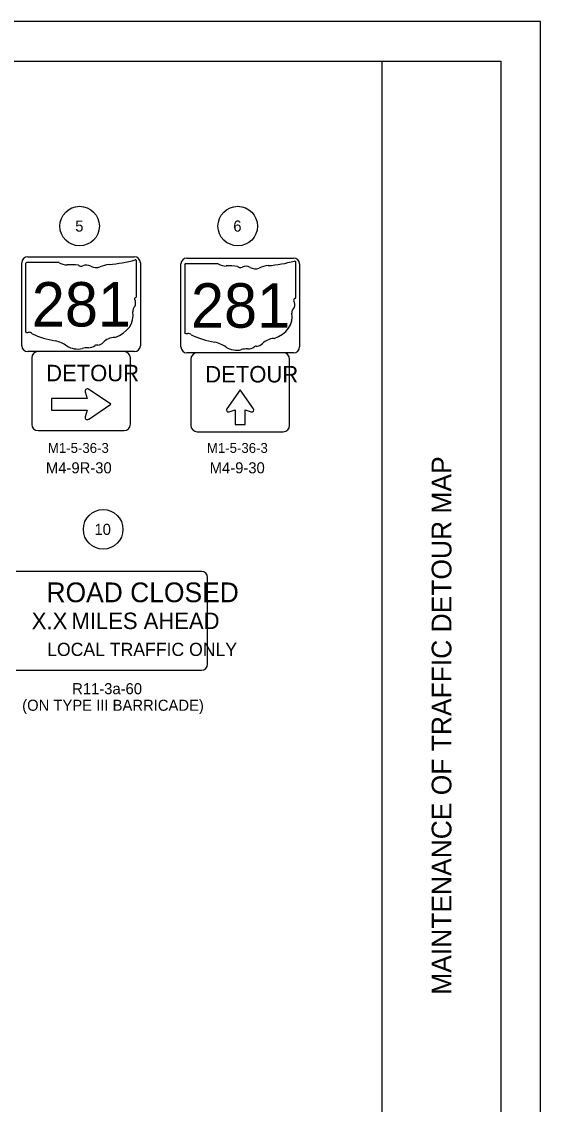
# Model space of a CAD drawing. Extents: x 0 to 680, y 0 to 834.
# Drawn here: x 548.7 to 680, y 165.9 to 440 of the extents above; entities that cross this region are included whole.
import ezdxf

# ---------------------------------------------------------------- set-up
doc = ezdxf.new("R2010")
doc.units = 0
for name, color, linetype in [('SH_Border', 7, 'Continuous'), ('SH_Cut_Line', 7, 'Continuous'), ('SH_Data', 7, 'Continuous'), ('SH_Text', 7, 'Continuous'), ('SN_P_Signs', 7, 'Continuous'), ('SN_P_Text', 7, 'Continuous'), ('SN_X_Public', 7, 'Continuous')]:
    doc.layers.add(name, color=color, linetype=linetype)

msp = doc.modelspace()

# ---------------------------------------------------------------- linework, layer by layer
at = {"layer": 'SH_Border'}
msp.add_line((640, 10), (640, 430), dxfattribs=at)
msp.add_lwpolyline([(30, 430), (670, 430), (670, 10), (30, 10)], close=True, dxfattribs=at)
at = {"layer": 'SH_Cut_Line'}
msp.add_lwpolyline([(0, 0), (680, 0), (680, 440), (0, 440)], close=True, dxfattribs=at)
at = {"layer": 'SH_Text'}
for centre in [(563.41, 388.25), (603.41, 388.25), (569.36, 311.46)]:
    msp.add_circle(centre, 5, dxfattribs=at)
at = {"layer": 'SN_P_Signs'}
for p, q in [((549.71, 378.68), (549.71, 361.61)), ((558.23, 378.98), (549.99, 378.98)), ((577.84, 370.47), (577.84, 379.4)), ((589.99, 378.39), (589.99, 361.31)), ((598.5, 378.68), (590.27, 378.68)), ((618.11, 370.17), (618.11, 379.1)), ((577.84, 370.47), (577.84, 370.47)), ((618.11, 370.17), (618.11, 370.17)), ((564.79, 346.28), (565.34, 344.58)), ((571.27, 343.12), (565.66, 346.93)), ((565.34, 344.58), (556.28, 344.58)), ((556.28, 344.58), (556.28, 341.66)), ((565.66, 339.31), (571.27, 343.12)), ((556.28, 341.66), (565.34, 341.66)), ((565.34, 341.66), (564.79, 339.96))]:
    msp.add_line(p, q, dxfattribs=at)
for points in [[(548.78, 357.95), (548.78, 378.95)], [(550.28, 380.45), (577.28, 380.45)], [(578.78, 378.95), (578.78, 357.95)], [(589.05, 357.65), (589.05, 378.65)], [(590.55, 380.15), (617.55, 380.15)], [(619.05, 378.65), (619.05, 357.65)], [(577.28, 356.45), (550.28, 356.45)], [(574.68, 356.45), (552.88, 356.45)], [(551.28, 354.85), (551.28, 338.05)], [(576.28, 338.05), (576.28, 354.85)], [(617.55, 356.15), (590.55, 356.15)], [(552.88, 336.45), (574.68, 336.45)], [(594.21, 300.79), (547.34, 300.79)], [(595.77, 277.35), (595.77, 299.23)], [(547.34, 275.79), (594.21, 275.79)]]:
    msp.add_lwpolyline(points, dxfattribs=at)
for centre, radius, start, end in [((550.28, 378.95), 1.5, 90, 180), ((577.28, 378.95), 1.5, 0, 90), ((590.55, 378.65), 1.5, 90, 180), ((617.55, 378.65), 1.5, 0, 90), ((550.28, 357.95), 1.5, 180, 270), ((552.88, 354.85), 1.6, 90, 180), ((574.68, 354.85), 1.6, 0, 90), ((577.28, 357.95), 1.5, 270, 0), ((590.55, 357.65), 1.5, 180, 270), ((617.55, 357.65), 1.5, 270, 0), ((565.34, 346.45), 0.572, 55.8031, 197.8008), ((565.34, 339.79), 0.572, 162.1992, 304.1969), ((552.88, 338.05), 1.6, 180, 270), ((574.68, 338.05), 1.6, 270, 0), ((594.21, 299.23), 1.56, 0, 90), ((594.21, 277.35), 1.56, 270, 0)]:
    msp.add_arc(centre, radius, start, end, dxfattribs=at)
for centre, major_axis, start_param, end_param in [((550.04, 378.72), (0.326, 0), 1.712693, 3.28349), ((560.19, 380.96), (3.16, 0), 4.042523, 4.731795), ((561.24, 369.39), (11.35, 0), 1.404758, 1.657858), ((563.81, 378.81), (0.912, 0), 3.836095, 5.185415), ((565.15, 376.84), (1.9, 0), 0.950623, 2.079405), ((571.62, 373.76), (6, 0), 1.699011, 2.107814), ((567.82, 402.26), (29.83, 0), 4.814394, 5.042369), ((577.53, 379.44), (0.313, 0), 6.141152, 7.989035), ((590.31, 378.42), (0.326, 0), 1.712693, 3.28349), ((600.46, 380.66), (3.16, 0), 4.042523, 4.731795), ((608.09, 401.96), (29.83, 0), 4.814394, 5.042369), ((617.8, 379.14), (0.313, 0), 6.141152, 7.989035), ((567.6, 379.54), (2.28, 0), 4.081561, 5.145723), ((601.51, 369.09), (11.35, 0), 1.404758, 1.657858), ((604.09, 378.51), (0.912, 0), 3.836095, 5.185415), ((605.43, 376.54), (1.9, 0), 0.950623, 2.079405), ((607.87, 379.25), (2.28, 0), 4.081561, 5.145723), ((611.9, 373.47), (6, 0), 1.699011, 2.107814), ((577.77, 369.81), (0.485, 0), 1.883978, 3.671073), ((577.5, 370.43), (0.335, 0), 5.05454, 6.418171), ((617.78, 370.14), (0.335, 0), 5.05454, 6.418171), ((578.96, 366.73), (2.12, 0), 2.387724, 3.262537), ((574.68, 368.68), (2.91, 0), 5.934695, 6.695948), ((619.24, 366.43), (2.12, 0), 2.387724, 3.262537), ((618.04, 369.52), (0.485, 0), 1.883978, 3.671073), ((614.96, 368.39), (2.91, 0), 5.934695, 6.695948), ((569.49, 365.59), (7.46, 0), 5.101752, 6.440018), ((609.77, 365.3), (7.46, 0), 5.101752, 6.440018), ((550.04, 361.57), (0.329, 0), 3.00124, 4.508301), ((550.09, 363.32), (2.51, 0), 4.665946, 4.897461), ((550.6, 360.62), (0.905, 0), 0.519207, 1.627899), ((562.02, 375.97), (21.54, 0), 4.195997, 4.488961), ((555.6, 353.94), (6.74, 0), 0.823519, 1.323587), ((572.64, 356.81), (4.09, 0), 1.647645, 2.488434), ((590.31, 361.27), (0.329, 0), 3.00124, 4.508301), ((590.36, 363.02), (2.51, 0), 4.665946, 4.897461), ((590.88, 360.32), (0.905, 0), 0.519207, 1.627899), ((602.3, 375.67), (21.54, 0), 4.195997, 4.488961), ((612.91, 356.52), (4.09, 0), 1.647645, 2.488434), ((562.89, 360.54), (4.28, 0), 4.026481, 4.996735), ((565.36, 354.63), (3.51, 0), 1.495662, 1.94098), ((565.67, 359.26), (2.28, 0), 4.691044, 5.507374), ((567.73, 357.6), (0.641, 0), 1.147584, 2.315152), ((567.46, 359.95), (2.41, 0), 4.937069, 5.64225), ((595.88, 353.64), (6.74, 0), 0.823519, 1.323587), ((603.16, 360.24), (4.28, 0), 4.026481, 4.996735), ((605.63, 354.34), (3.51, 0), 1.495662, 1.94098), ((605.95, 358.96), (2.28, 0), 4.691044, 5.507374), ((608.01, 357.31), (0.641, 0), 1.147584, 2.315152), ((607.73, 359.66), (2.41, 0), 4.937069, 5.64225)]:
    msp.add_ellipse(centre, major_axis=major_axis, ratio=0.8, start_param=start_param, end_param=end_param, dxfattribs=at)
at = {"layer": 'SN_X_Public'}
for p, q in [((604.05, 346.75), (600.7, 341.97)), ((607.41, 341.97), (604.05, 346.75)), ((601.25, 341.22), (602.79, 341.71)), ((602.79, 341.71), (602.79, 341.69)), ((602.79, 341.69), (602.79, 338)), ((605.32, 341.71), (606.86, 341.22)), ((602.79, 338), (605.32, 338))]:
    msp.add_line(p, q, dxfattribs=at)
for points in [[(591.55, 354.55), (591.55, 337.75)], [(614.95, 356.15), (593.15, 356.15)], [(616.55, 337.75), (616.55, 354.55)], [(605.32, 338), (605.32, 341.69)], [(593.15, 336.15), (614.95, 336.15)]]:
    msp.add_lwpolyline(points, dxfattribs=at)
for centre, radius, start, end in [((593.15, 354.55), 1.6, 90, 180), ((614.95, 354.55), 1.6, 0, 90), ((601.1, 341.69), 0.493, 144.9207, 287.6378), ((607.01, 341.69), 0.493, 252.3622, 35.0792), ((593.15, 337.75), 1.6, 180, 270), ((614.95, 337.75), 1.6, 270, 0)]:
    msp.add_arc(centre, radius, start, end, dxfattribs=at)

# ---------------------------------------------------------------- texts
at = {"layer": 'SH_Data'}
msp.add_text('MAINTENANCE OF TRAFFIC DETOUR MAP', height=5, rotation=90, dxfattribs=at).set_placement((657.5, 193.62))
at = {"layer": 'SH_Text'}
for s, height, p in [('5', 2.8, (562.29, 386.85)), ('6', 2.8, (602.3, 386.85)), ('10', 2.8, (567.16, 310.06)), ('X.X', 4.2, (551.27, 286.17))]:
    msp.add_text(s, height=height, dxfattribs=at).set_placement(p)
at = {"layer": 'SN_P_Signs'}
for s, height, p in [('281', 11.25, (551.31, 362.81)), ('281', 11.25, (591.58, 362.51)), ('DETOUR', 4.167, (554.93, 348.95)), ('ROAD CLOSED', 5, (555.02, 293.01)), ('MILES AHEAD', 4.1667, (561.35, 286.21)), ('LOCAL TRAFFIC ONLY', 3.3333, (555.19, 279.4))]:
    msp.add_text(s, height=height, dxfattribs=at).set_placement(p)
at = {"layer": 'SN_P_Text'}
for s, height, p in [('M1-5-36-3', 2.5, (555.37, 330.82)), ('M1-5-36-3', 2.5, (595.61, 330.82)), ('M4-9R-30', 2.8, (554.88, 325.64)), ('M4-9-30', 2.8, (596.32, 325.64)), ('R11-3a-60', 2.8, (561.51, 269.72)), ('(ON TYPE III BARRICADE)', 2.8, (548.87, 265.52))]:
    msp.add_text(s, height=height, dxfattribs=at).set_placement(p)
at = {"layer": 'SN_X_Public'}
msp.add_text('DETOUR', height=4.167, dxfattribs=at).set_placement((595.2, 348.65))

doc.saveas('drawing.dxf')
